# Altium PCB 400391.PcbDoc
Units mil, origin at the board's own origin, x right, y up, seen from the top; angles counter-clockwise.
Board outline 990.33 x 2250.13 mil, 2 copper layers (Top Layer, Bottom Layer), stack 39.414 mil thick; 7 components, 18 nets, 52 pads, 82 vias.
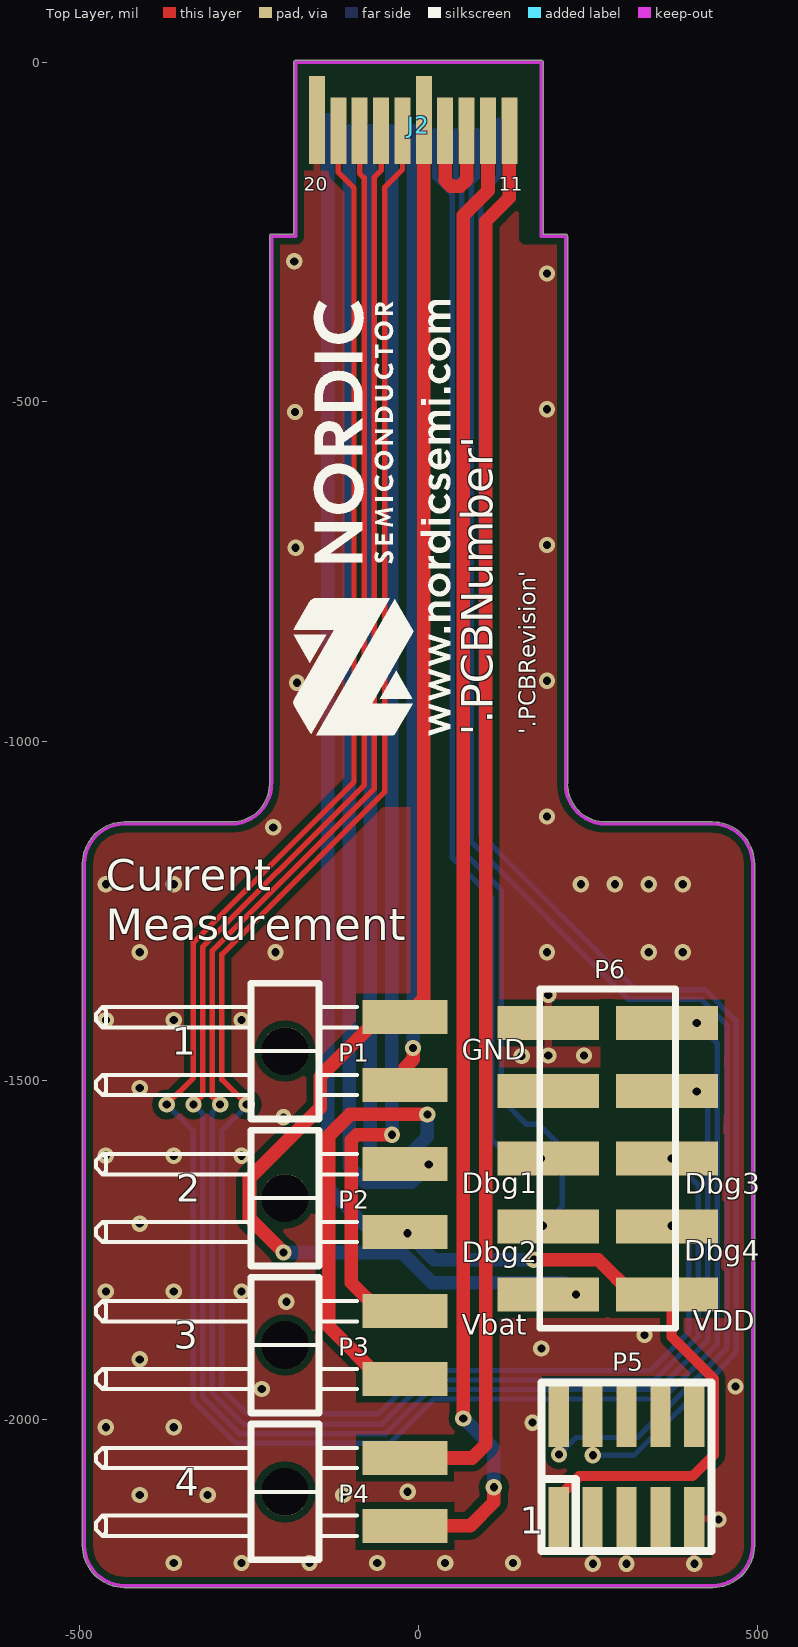
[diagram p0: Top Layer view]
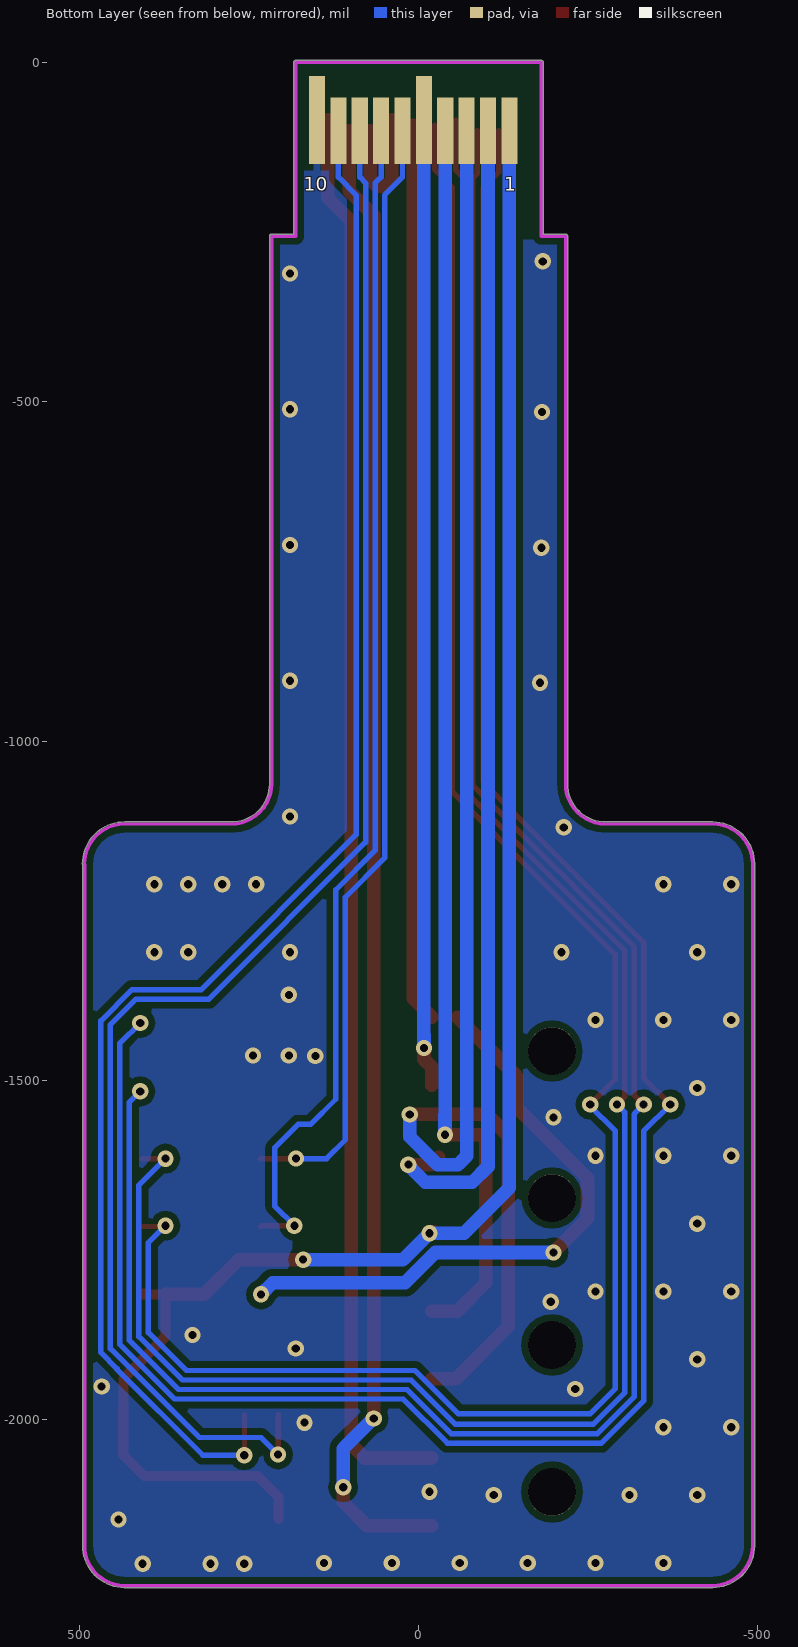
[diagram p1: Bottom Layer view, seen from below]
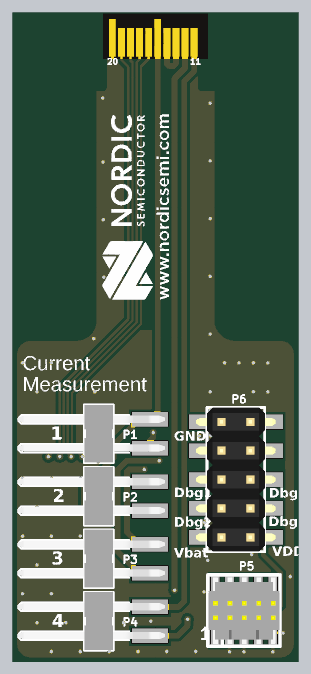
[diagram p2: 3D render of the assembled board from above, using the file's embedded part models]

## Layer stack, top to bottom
Top Solder: solder mask 0.4, Solder Resist, Dk 3.5
Top Layer: signal copper 1.4
Dielectric1: core 36.6142, FR-4, Dk 4.8
Bottom Layer: signal copper 1.4
Bottom Solder: solder mask 0.4, Solder Resist, Dk 3.5

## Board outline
-495.14,-2185.04 -495.14,-1181.1 -495.13,-1180.88 cw(c-433.07,-1181.1) -433.29,-1119.04 -433.07,-1119.03 -275.59,-1119.03 -275.38,-1119.04 ccw(c-275.59,-1062.99) -219.54,-1063.2 -219.55,-1062.99 -219.55,-255.91 cw(c-216.54,-255.91) -216.54,-252.89 -184.12,-252.89 -184.12,0 cw(c-181.1,0) -181.1,3.02 181.1,3.02 cw(c181.1,0) 184.12,0 184.12,-252.89 216.54,-252.89 cw(c216.54,-255.91) 219.55,-255.91 219.55,-1062.99 219.54,-1063.2 ccw(c275.59,-1062.99) 275.38,-1119.04 275.59,-1119.03 432.59,-1119.03 433.13,-1118.98 cw(c433.13,-1181.05) 495.19,-1181.05 495.14,-1181.59 495.14,-2185.04 495.13,-2185.26 cw(c433.07,-2185.04) 433.29,-2247.1 433.07,-2247.11 -433.07,-2247.11 -433.29,-2247.1 cw(c-433.07,-2185.04)

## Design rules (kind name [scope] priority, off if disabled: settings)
Clearance ANT_Clerance [InNet('ANT')] p1: gap=5 ignorepadtopadclearanceinfootprint=FALSE except(0: Arc-Hole Track-Hole SMDPad-Hole THPad-Hole Via-Hole Fill-Hole Poly-Hole Region-Hole Text-Hole)
Clearance Polygon_Clearance [(InNamedPolygon('Top_Layer-GND')) or (InNamedPolygon('Bottom_Layer-GND'))] p2: gap=10 ignorepadtopadclearanceinfootprint=FALSE except(0: Arc-Hole Track-Hole SMDPad-Hole THPad-Hole Via-Hole Fill-Hole Poly-Hole Region-Hole Text-Hole)
Clearance [All] p3: gap=6 ignorepadtopadclearanceinfootprint=FALSE except(0: Arc-Hole Track-Hole SMDPad-Hole THPad-Hole Via-Hole Fill-Hole Poly-Hole Region-Hole Text-Hole)
ComponentClearance [All] p1 off: gap=10 collisioncheckmode=3 verticalgap=10 showdistances=FALSE
DiffPairsRouting [All] p1: maxlimit=5.91 minlimit=5.91 mostfreqgap=5.91 toplayer_minwidth=15 toplayer_maxwidth=15 toplayer_prefwidth=15 bottomlayer_minwidth=15 bottomlayer_maxwidth=15 bottomlayer_prefwidth=15 maxuncoupledlength=500
FabricationTestPointUsage TestPointUsage [All] p1: valid=0 allowmultiple=FALSE
FabricationTestpoint Testpoint [All] p1: side=3 testpointundercomponent=TRUE minsize=40 maxsize=100 preferedsize=60 minholesize=0 maxholesize=40 preferedholesize=32 testpointgrid=1 allowsidetop=TRUE allowsidebottom=TRUE usegrid=TRUE gridtolerance=0.01
Height [All] p1 off: minheight=0 maxheight=1000 prefheight=500
HoleSize [All] p1: absolutevalues=TRUE maxlimit=196.85 minlimit=12 maxpercent=80.000 minpercent=20.000
MinimumAnnularRing [All] p1 off: minimumring=6
PolygonConnect PolygonConnect_1 [isVia and innet(gnd)] p1: connectstyle=Direct reliefconductorwidth=10 reliefentries=4 polygonreliefangle="90 Angle" airgapwidth=10
PolygonConnect [All] p2: connectstyle=Relief reliefconductorwidth=10 reliefentries=4 polygonreliefangle="90 Angle" airgapwidth=10
RoutingVias [All] p1: holewidth=12 width=24 viastyle="Through Hole" minholewidth=12 minwidth=24 maxholewidth=12 maxwidth=24
SilkToSolderMaskClearance SilkscreenOverComponentPads [IsPad] p1: minsilkscreentomaskgap=10 clearancetoexposedcopper=TRUE
SolderMaskExpansion [All] p1: expansion=3 istentingtop=FALSE
Width [All] p1: maxlimit=100 minlimit=8 preferedwidth=15
23 further rules are at their usual default settings.

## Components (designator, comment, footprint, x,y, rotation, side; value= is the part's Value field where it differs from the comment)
J2 "Card Edge, 0.8mm" "10056847-101LF Mating Board" 0,0 r0 top locked
P1 "Pin List 1x2, Angled" LIST_ANG_1x2-SMD-2.54MM -19.68,-1456.69 r270 top locked
P2 "Pin List 1x2, Angled" LIST_ANG_1x2-SMD-2.54MM -19.68,-1673.23 r270 top locked
P3 "Pin List 1x2, Angled" LIST_ANG_1x2-SMD-2.54MM -19.68,-1889.76 r270 top locked
P4 "Pin List 1x2, Angled" LIST_ANG_1x2-SMD-2.54MM -19.68,-2106.3 r270 top locked
P5 "Pin Header 2x5, 1.27mm" HDR_2x5-SMD-1.27mm-K 306.5,-2069.33 r0 top
P6 "Pin Hdr 2x5" HDR_2x5-SMD 278.59,-1615.17 r90 top

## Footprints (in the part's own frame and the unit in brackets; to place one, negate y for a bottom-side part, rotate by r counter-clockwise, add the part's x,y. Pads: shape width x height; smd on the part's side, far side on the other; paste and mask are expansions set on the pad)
"10056847-101LF Mating Board" [mm]
  rect 0.6x2.5 smd far side paste-1 mask+0.025: 1(-3.4,-2.55) 2(-2.6,-2.55) 3(-1.8,-2.55) 4(-1,-2.55) 6(0.6,-2.55) 7(1.4,-2.55) 8(2.2,-2.55) 9(3,-2.55)
  rect 0.6x3.3 smd far side paste-1 mask+0.025: 5(-0.2,-2.15) 10(3.8,-2.15)
  rect 0.6x2.5 smd paste-1 mask+0.025: 11(3.4,-2.55) 12(2.6,-2.55) 13(1.8,-2.55) 14(1,-2.55) 16(-0.6,-2.55) 17(-1.4,-2.55) 18(-2.2,-2.55) 19(-3,-2.55)
  rect 0.6x3.3 smd paste-1 mask+0.025: 15(0.2,-2.15) 20(-3.8,-2.15)
  Keep-Out Layer lines w0.127: -4.6,-6.5 -4.6,0 4.6,0 4.6,-6.5
HDR_2x5-SMD [mil] "Board-Board Conn, Header, 10-way, 2-row"
  rect 50x150 smd: 1(-200,-87.5) 2(-200,87.5) 3(-100,-87.5) 4(-100,87.5) 5(0,-87.5) 6(0,87.5) 7(100,-87.5) 8(100,87.5) 9(200,-87.5) 10(200,87.5)
  silkscreen extent -250,-100 250,100, body extent -250,-138 250,138, height 380
HDR_2x5-SMD-1.27mm-K [mm] "SMT MICRO HEADER, (1,27) .050\" Keying Shroud"
  rect 0.76x2.4 smd: 1(-2.54,-1.95) 2(-2.54,1.95) 3(-1.27,-1.95) 4(-1.27,1.95) 5(0,-1.95) 6(0,1.95) 7(1.27,-1.95) 8(1.27,1.95) 9(2.54,-1.95) 10(2.54,1.95)
  silkscreen extent -3.17,-3.15 3.18,3.15, body extent -3.14,-2.92 3.14,2.92, height 6.11
LIST_ANG_1x2-SMD-2.54MM [mm] "Pin List, 2.54mm, Surface Mount, Angled"
  round 1.78 hole 1.78 unplated: 0(0,-4.496)
  rect 1.27x3.18 smd: 1(-1.27,0) 2(1.27,0)
  silkscreen extent -2.54,-11.58 2.54,-1.8, body extent -2.56,-11.61 2.52,1.35, height 3.03

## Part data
J2: library part "10056847-101LF Mating Board", "0.8mm pitch, dual edge, card edge connector", Part number IPS=N.A.
P1 P2 P3 P4: library part "Pin List Ang 1x2 SMD, 2.54mm", "Pin List 1x2, 2.54mm (100mil), Right Angled, SMD", Manufacturer=W-CON, Manufacturer Part Number=1125B-1102S0Z135R2, Part number IPS=N.A.
P5: library part "Pin Header 2x5 SMD, 1.27mm, KS", "Pin Header 2x5, 1.27mm (50mil), SMD, Keying Shroud", Manufacturer=W-CON, Manufacturer Part Number=3132-10MS0BK00R1, Part number IPS=N.A.
P6: library part "Pin Header 2x5 SMD", "Pin Header 2x5, 2.54mm (100mil) SMD", Manufacturer=Molex, Manufacturer Part Number=15-91-2100, Part number IPS=N.A., Supplier Part Number 1=142-1678

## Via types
v1: diameter 24, hole 12, Top Layer to Bottom Layer, tented both sides, 82 vias

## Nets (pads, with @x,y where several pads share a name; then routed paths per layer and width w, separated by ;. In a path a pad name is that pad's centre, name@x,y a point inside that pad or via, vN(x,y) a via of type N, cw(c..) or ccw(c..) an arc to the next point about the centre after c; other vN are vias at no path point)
DBG1: J2.6 P6.6 | length 1659.9
  Top Layer w8: v1(180.45,-1615) 233,-1615 233.17,-1615.17 P6.6@232.09,-1615.17
  Bottom Layer w8: J2.6 23.62,-169 49.87,-195.24 49.87,-1171.87 108,-1230 108,-1587.69 135.31,-1615 v1(180.45,-1615)
DBG2: J2.7 P6.4 | length 1753.1
  Top Layer w8: v1(183,-1714) 232,-1714 233.17,-1715.17 P6.4@232.09,-1715.17
  Bottom Layer w8: J2.7 55.12,-169 63.87,-177.75 63.87,-1160.87 122,-1219 122,-1527.62 159.06,-1564.69 177.37,-1564.69 212,-1599.31 212,-1685 v1(183,-1714)
DBG3: J2.17 P6.5 | length 3087.6
  Top Layer w8: -303.67,-1524.04 v1(-292.33,-1535.37) ; -303.67,-1523 -303.67,-1308.47 -65,-1069.8 -65,-168.76 -55.12,-158.88 J2.17@-55.12,-84.65 ; v1(373,-1615.17) 404.09,-1615.17 P6.5@407.09,-1615.17
  Bottom Layer w8: v1(-292.33,-1535.37) -303.67,-1546.7 -303.67,-1960.43 -257.79,-2006.3 -53.93,-2006.3 11,-1941.37 348,-1941.37 412,-1877.37 412,-1654.17 v1(373,-1615.17)
DBG4: J2.16 P6.3 | length 2955.7
  Top Layer w8: v1(-253,-1535.37) -289.67,-1498.7 -289.67,-1314.26 -50,-1074.6 -50,-184 -23.62,-157.62 J2.16@-23.62,-92.52 ; v1(373,-1714) 374.17,-1715.17 404.09,-1715.17 P6.3@407.09,-1715.17
  Bottom Layer w8: v1@-253,-1537.37 -289.67,-1574.04 -289.67,-1954.63 -252.92,-1991.37 -58.8,-1991.37 5.2,-1927.37 342.2,-1927.37 398,-1871.57 398,-1739 v1(373,-1714)
GND: J2.10 J2.20 P5.3 P5.5 P5.9 P6.10
  other v1: 256.89,-2212 306.5,-2212 406.5,-2212 -360.72,-2210.93 -260.72,-2210.93 -160.72,-2210.93 -60.72,-2210.93 39.28,-2210.93 139.28,-2210.93 442,-2147 -410.72,-2110.93 -310.72,-2110.93 -110.72,-2110.93 -16,-2106 -460.72,-2010.93 -360.72,-2010.93 168,-2004.13 -231,-1954.63 467,-1951 -410.72,-1910.93 181,-1895 333,-1875 -194.76,-1826 -460.72,-1810.93 -360.72,-1810.93 -260.72,-1810.93 -410.72,-1710.93 -460.72,-1610.93 -360.72,-1610.93 -260.72,-1610.93 -199,-1554.31 -410.72,-1510.93 152,-1464 191.09,-1463.11 244,-1463.11 -460.72,-1410.93 -360.72,-1410.93 -260.72,-1410.93 191.09,-1373.83 -410.72,-1310.93 -210.72,-1310.93 189.28,-1310.93 339.28,-1310.93 389.28,-1310.93 -460.72,-1210.93 -360.72,-1210.93 239.28,-1210.93 289.28,-1210.93 339.28,-1210.93 389.28,-1210.93 -214,-1127 189.28,-1110.93 -179,-914 189.28,-910.93 -181,-715 189.28,-710.93 -182,-515 189.28,-510.93 189.28,-310.93 -183,-293
NetJ2_13: J2.13 J2.14 | length 200.5
  Top Layer w20: J2.14@39.37,-84.65 39.37,-173.71 47.86,-182.2 61.67,-182.2 70.87,-173 J2.13
NetJ2_18: J2.18 P6.7 | length 3178.8
  Top Layer w8: v1(-331.67,-1535.37) -317.67,-1521.37 -317.67,-1302.67 -228.08,-1213.08 -228.08,-1212.63 -207,-1191.55 -206.55,-1191.55 -80,-1065 -80,-170 -86.61,-163.39 J2.18 ; P6.7@407.09,-1515.17 409.17,-1515.17 v1(410,-1516)
  Bottom Layer w8: v1(-331.67,-1535.37) -317.67,-1549.37 -317.67,-1966.22 -263.59,-2020.3 -48.13,-2020.3 16.8,-1955.37 353.8,-1955.37 426,-1883.17 426,-1532 v1(410,-1516)
NetJ2_19: J2.19 P6.9 | length 3359.1
  Top Layer w8: v1(-371,-1535.37) -331.67,-1496.04 -331.67,-1296.42 -95.25,-1060 -95,-1060 -95,-185 -118.11,-161.89 J2.19 ; P6.9@407.09,-1415.17 v1(410,-1415.17)
  Bottom Layer w8: v1(-371,-1535.37) -331.67,-1574.7 -331.67,-1972.02 -269.39,-2034.3 -42.33,-2034.3 22.6,-1969.37 359.6,-1969.37 440,-1888.97 440,-1445 410,-1415 v1(410,-1415.17)
SWCLK: J2.9 P5.4 | length 2376.9
  Top Layer w8: P5.4 256.5,-2051.81 v1(256.89,-2052.2)
  Bottom Layer w8: J2.9@118.11,-84.65 118.11,-169 91.87,-195.24 91.87,-1137.87 320,-1366 422,-1366 468,-1412 468,-1900.8 444,-1924.8 444,-1926 317.8,-2052.2 v1(256.89,-2052.2)
SWDIO: J2.8 P5.2 | length 2387.1
  Top Layer w8: P5.2 207,-1993.06 v1(207,-2051)
  Bottom Layer w8: J2.8 86.61,-169 77.87,-177.75 77.87,-1148.87 309,-1380 416.2,-1380 454,-1417.8 454,-1895 323,-2026 232,-2026 v1(207,-2051)
VBAT: J2.15 P1.1 P6.2 | length 2229.6
  Top Layer w20: v1(-199,-1753.5) -199,-1753 -249,-1703 -249,-1644 -145,-1540 -145,-1494.28 P1.1@-57.42,-1406.69 ; P1.1 7.87,-1379.13 7.87,-1123.23 J2.15@7.87,-92.52
  Bottom Layer w20: v1@-199.5,-1753.5 v1(-199,-1753.5) -24.5,-1753.5 20,-1798 214.92,-1798 v1(232.09,-1815.17)
VBAT': J2.5 P1.2 | length 1411.2
  Top Layer w20: P1.2 -19.69,-1480.64 -8,-1468.95 v1(-8,-1452)
  Bottom Layer w20: v1(-8,-1452) -8,-1433.2 -7.87,-1433.08 -7.87,-1198.74 -7.87,-1162 J2.5@-7.87,-100.39
VBUS: J2.4 P3.1 | length 1849.7
  Top Layer w20: v1(-39,-1580) -91,-1580 -99,-1588 -99,-1798 -57.24,-1839.76 P3.1
  Bottom Layer w20: J2.4 -39.37,-1111 -39.37,-1159.37 -39.37,-1550.63 -39,-1551 v1(-39,-1580)
VBUS': J2.3 P3.2 | length 2233.9
  Top Layer w20: P3.2 -55.24,-1939.76 -132,-1863 -132,-1581 -101,-1550 v1(13,-1550)
  Bottom Layer w20: J2.3 -70.87,-1141 -70.87,-1611.13 -58,-1624 -28,-1624 13,-1583 v1(13,-1550)
VDD_LED: J2.11 P4.1 | length 2093.2
  Top Layer w20: P4.1 79.07,-2056.3 99.37,-2036 99.26,-2035.89 99.26,-1971 99.26,-234 133.86,-199.4 J2.11@133.86,-84.65
VDD_LED': J2.12 P4.2 | length 2201.3
  Top Layer w20: P4.2 76.07,-2156.3 111,-2121.37 v1(111,-2099.37) ; v1(66,-1998.19) 66,-1997.37 66,-225.36 102.36,-189 J2.12
  Bottom Layer w20: v1(66,-1998.19) 66.81,-1998.19 111,-2042.37 v1(111,-2099.37) v1@111,-2100.37
VDD_nRF: J2.2 P2.1 | length 1714.4
  Top Layer w20: P2.1@-30,-1612.91 P2.1 -18.91,-1624 v1(15,-1624)
  Bottom Layer w20: J2.2 -102.36,-1170 -102.36,-1205.16 -102.36,-1626.87 -79.23,-1650 -10,-1650 15,-1625 v1(15,-1624)
VDD_nRF': J2.1 P2.2 P5.1 P6.1 | length 2739.9
  Top Layer w15: P5.1 206.5,-2113.24 236.74,-2083 403.74,-2083 435,-2051.74 435,-1984.69 434.96,-1984.64 434.96,-1939.72 373,-1877.76 P6.1@373,-1816 ; P6.1@405,-1814.17 P6.1@405,-1815.17 ; P6.1@407.09,-1815.17 P6.1@405,-1815.17 ; P6.1@373,-1816 373,-1815.17 P6.1@373.83,-1815.17 ; P6.1@373,-1816 P6.1@373.83,-1815.17 ; P6.1@373.83,-1815.17 P6.1@405,-1815.17
  Top Layer w20: P2.2 -22.05,-1723.23 -20.28,-1725 v1(-16,-1725) ; v1(170,-1764) 265,-1764 316.17,-1815.17 P6.1 P6.1@373,-1815.17
  Bottom Layer w20: J2.1@-133.86,-84.65 -133.86,-1159.37 -133.86,-1198.74 -133.86,-1658.14 -67,-1725 v1(-16,-1725) 23,-1764 v1(170,-1764)
pads on no net: P1.0 P2.0 P3.0 P4.0 P5.6 P5.7 P5.8 P5.10 P6.8

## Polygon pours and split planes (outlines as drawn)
GND on Top Layer "Top_Layer-GND" (solid, remove dead copper, pour order 41): -495.14,-2185.04 -495.14,-1181.1 -495.13,-1180.88 cw(c-433.07,-1181.1) -433.29,-1119.04 -433.07,-1119.03 -275.59,-1119.03 -275.38,-1119.04 ccw(c-275.59,-1062.99) -219.54,-1063.2 -219.55,-1062.99 -219.55,-255.91 cw(c-216.54,-255.91) -216.54,-252.89 -184.12,-252.89 -184.12,0 cw(c-181.1,0) -181.1,3.02 181.1,3.02 cw(c181.1,0) 184.12,0 184.12,-252.89 216.54,-252.89 cw(c216.54,-255.91) 219.55,-255.91 219.55,-1062.99 219.54,-1063.2 ccw(c275.59,-1062.99) 275.38,-1119.04 275.59,-1119.03 432.59,-1119.03 433.13,-1118.98 cw(c433.13,-1181.05) 495.19,-1181.05 495.14,-1181.59 495.14,-2185.04 495.13,-2185.26 cw(c433.07,-2185.04) 433.29,-2247.1 433.07,-2247.11 -433.07,-2247.11 -433.29,-2247.1 cw(c-433.07,-2185.04)
GND on Bottom Layer "Bottom_Layer-GND" (solid, remove dead copper, pour order 42): -495.14,-2185.04 -495.14,-1181.1 -495.13,-1180.88 cw(c-433.07,-1181.1) -433.29,-1119.04 -433.07,-1119.03 -275.59,-1119.03 -275.38,-1119.04 ccw(c-275.59,-1062.99) -219.54,-1063.2 -219.55,-1062.99 -219.55,-255.91 cw(c-216.54,-255.91) -216.54,-252.89 -184.12,-252.89 -184.12,0 cw(c-181.1,0) -181.1,3.02 181.1,3.02 cw(c181.1,0) 184.12,0 184.12,-252.89 216.54,-252.89 cw(c216.54,-255.91) 219.55,-255.91 219.55,-1062.99 219.54,-1063.2 ccw(c275.59,-1062.99) 275.38,-1119.04 275.59,-1119.03 432.59,-1119.03 433.13,-1118.98 cw(c433.13,-1181.05) 495.19,-1181.05 495.14,-1181.59 495.14,-2185.04 495.13,-2185.26 cw(c433.07,-2185.04) 433.29,-2247.1 433.07,-2247.11 -433.07,-2247.11 -433.29,-2247.1 cw(c-433.07,-2185.04)

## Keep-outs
Keep-Out Layer:
  lines w5: 433.07,-1122.05 275.59,-1122.05 cw(c275.59,-1062.99) 216.54,-1062.99 216.54,-255.91 181.1,-255.91 181.1,0 -181.1,0 -181.1,-255.91 -216.54,-255.91 -216.54,-1062.99 cw(c-275.59,-1062.99) -275.59,-1122.05 -433.07,-1122.05 ccw(c-433.07,-1181.1) -492.13,-1181.1 -492.13,-2185.04 ccw(c-433.07,-2185.04) -433.07,-2244.1 433.07,-2244.1 ccw(c433.07,-2185.04) 492.13,-2185.04 492.13,-1181.1 ; 433.13,-1121.99 cw(c433.13,-1181.05) 492.18,-1181.05

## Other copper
Top Layer:
  pour cut-out: 450.15,-1449
  pour cut-out: 450.15,-1449 451,-1449 446.18,-1784 445.18,-1783
  pour cut-out: 289.36,-1379.85 268,-1379.85 268,-1490 289.36,-1490
  pour cut-out: 285,-1849.17 284.83,-1849 271,-1849 271,-1841 270,-1840 271.24,-1838.76 285,-1838.76
  pour cut-out: 179.14,-268.29 154.29,-268.29 148,-262 148,-214 167.96,-214 170.96,-217
  pour cut-out: -56,-1097.37 -7.87,-1097.37 -7.87,-1085.5 -9,-1084.37 -45.74,-1084.37
Bottom Layer:
  pour cut-out: 184.87,-1748 186.28,-1746.6 186.28,-1733 180,-1733 179,-1732 178,-1733 178,-1749.37
  pour cut-out: -150,-165 -151,-166 -173,-166 -173,-260 -172.22,-260.78 -152,-260.78

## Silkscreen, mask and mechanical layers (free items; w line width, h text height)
Top Overlay:
  drawing of 43 lines, arcs and shapes, not listed
  text "'.PCBRevision'" at 172.51,-989.88 h25 r90
  text "'.PCBNumber'" at 124.51,-991.88 h80 r90
  text "Current" at -461,-1236 h80
  text "Measurement" at -461,-1309 h80
  text "1" at -363.7,-1476.38 h70
  text "GND" at 63.98,-1480.1 h51.18
  text "Dbg1" at 63.98,-1676.24 h51.18
  text "Dbg3" at 392.27,-1677.17 h51.18
  text "2" at -357.05,-1692.91 h70
  text "Dbg4" at 391.59,-1776.17 h51.18
  text "Dbg2" at 63.98,-1778.17 h51.18
  text "VDD" at 404.24,-1879.17 h51.18
  text "Vbat" at 63.98,-1884.69 h51.18
  text "3" at -360.87,-1909.45 h70
  text "4" at -359.39,-2125.98 h70
Board Outline:
  lines w5: -495.13,-2185.26 cw(c-492.13,-2185.04) -495.14,-2185.04 -495.14,-1181.1 cw(c-492.13,-1181.1) -495.13,-1180.88 cw(c-433.07,-1181.1) -433.29,-1119.04 cw(c-433.07,-1122.05) -433.07,-1119.03 -275.59,-1119.03 cw(c-275.59,-1122.05) -275.38,-1119.04 ccw(c-275.59,-1062.99) -219.54,-1063.2 cw(c-216.54,-1062.99) -219.55,-1062.99 -219.55,-255.91 cw(c-216.54,-255.91) -216.54,-252.89 -184.12,-252.89 -184.12,0 cw(c-181.1,0) -181.1,3.02 181.1,3.02 cw(c181.1,0) 184.12,0 184.12,-252.89 216.54,-252.89 cw(c216.54,-255.91) 219.55,-255.91 219.55,-1062.99 cw(c216.54,-1062.99) 219.54,-1063.2 ccw(c275.59,-1062.99) 275.38,-1119.04 cw(c275.59,-1122.05) 275.59,-1119.03 432.59,-1119.03 cw(c433.13,-1121.99) 433.13,-1118.98 cw(c433.13,-1181.05) 495.19,-1181.05 cw(c492.18,-1181.05) 495.14,-1181.59 495.14,-2185.04 cw(c492.13,-2185.04) 495.13,-2185.26 cw(c433.07,-2185.04) 433.29,-2247.1 cw(c433.07,-2244.1) 433.07,-2247.11 -433.07,-2247.11 cw(c-433.07,-2244.1) -433.29,-2247.1 cw(c-433.07,-2185.04) -495.13,-2185.26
